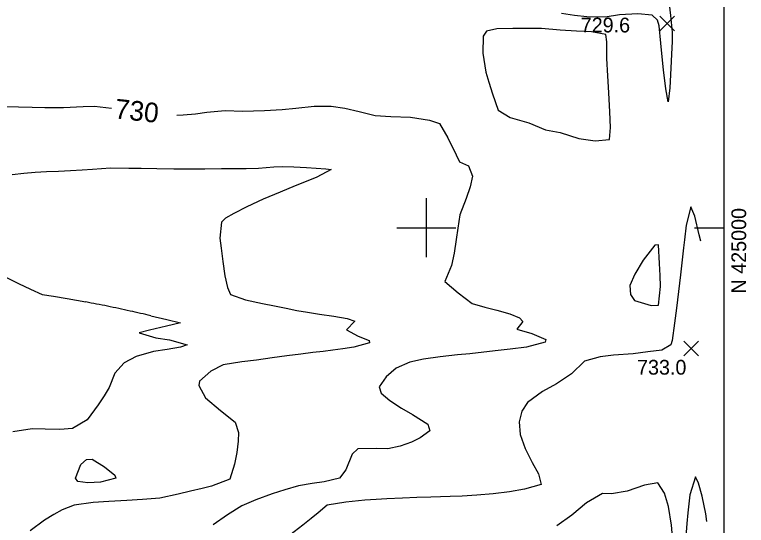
# Model space of a CAD drawing. Extents: x 2566079 to 2571326, y 424054 to 426896.
# Drawn here: x 2570581 to 2571326, y 424697 to 425217 of the extents above; entities that cross this region are included whole.
import ezdxf

# ---------------------------------------------------------------- set-up
doc = ezdxf.new("R2010")
doc.units = 0
for name, color, linetype in [('Contour_ADS_Label_Major', 7, 'Continuous'), ('Contour_ADS_Major', 7, 'Continuous'), ('Contour_ADS_Minor', 7, 'Continuous'), ('Contour_ADS_Spot_Elevation', 7, 'Continuous'), ('Contour_ADS_State_Plane_Border', 7, 'Continuous'), ('Contour_ADS_Tick', 7, 'Continuous')]:
    doc.layers.add(name, color=color, linetype=linetype)

# ---------------------------------------------------------------- blocks, each defined once
blk = doc.blocks.new('S890')
at = {"layer": 'Contour_ADS_Tick'}
for p, q in [((0, -0.5), (0, 0.5)), ((-0.5, 0), (0.5, 0))]:
    blk.add_line(p, q, dxfattribs=at)
blk = doc.blocks.new('S750')
at = {"layer": 'Contour_ADS_Spot_Elevation'}
for p, q in [((-0.5, 0.498), (0.5, -0.498)), ((-0.498, -0.5), (0.498, 0.5))]:
    blk.add_line(p, q, dxfattribs=at)

msp = doc.modelspace()

# ---------------------------------------------------------------- linework, layer by layer
at = {"layer": 'Contour_ADS_Major'}
for points in [[(2571247.16, 425227.51), (2571248.61, 425215.93), (2571250.07, 425199.08), (2571250.04, 425189.46), (2571249.56, 425176.51), (2571248.86, 425162.4), (2571247.71, 425142.46), (2571245.95, 425127.89), (2571243.63, 425141.31), (2571241.46, 425160.46), (2571240.06, 425173.97), (2571238.68, 425187.77), (2571237.04, 425205.47), (2571235.13, 425211.2), (2571229.74, 425216.37), (2571215.17, 425217.57), (2571196.61, 425216.58), (2571182, 425214.26), (2571163.35, 425214.64), (2571150.86, 425215.85), (2571137.48, 425217.8)], [(2570572.43, 425123.44), (2570584.86, 425122.91), (2570598.88, 425122.54), (2570611.93, 425122.33), (2570630.89, 425122.44), (2570650.66, 425123.4), (2570662.17, 425123.68), (2570679.69, 425121.7)], [(2570745.97, 425114.46), (2570752.47, 425114.71), (2570765.15, 425116.01), (2570776.61, 425117.61), (2570795.45, 425119.18), (2570813.15, 425118.71), (2570824, 425118.76), (2570835.27, 425119.11), (2570853.17, 425120.23), (2570867.04, 425121.75), (2570885.73, 425123.56), (2570903.1, 425123.76), (2570917.15, 425121.65), (2570931.79, 425118.29), (2570947.81, 425114.11), (2570963.77, 425113.03), (2570983.73, 425112.49), (2571003.3, 425109.32), (2571013.43, 425106.14), (2571021.97, 425091.45), (2571030.4, 425074.17), (2571033.81, 425066.9), (2571042.86, 425063.06), (2571046.9, 425052.34), (2571044.71, 425041.64), (2571040.63, 425029.6), (2571033.94, 425013.24), (2571031.92, 424999.7), (2571030.5, 424988.04), (2571028.3, 424974.02), (2571025.5, 424961.39), (2571018.8, 424945.4), (2571032.33, 424933.78), (2571046.66, 424922.84), (2571059.67, 424919.06), (2571071.8, 424916.03), (2571084.9, 424912.26), (2571094.73, 424908.29), (2571098.28, 424904.59), (2571092.1, 424896.92), (2571107.21, 424892.38), (2571121.6, 424886.2), (2571120.91, 424883.46), (2571102.05, 424878.39), (2571085.45, 424876.39), (2571072.92, 424874.98), (2571058.57, 424873.38), (2571044.31, 424871.83), (2571031.8, 424870.51), (2571014.09, 424868.68), (2570997.23, 424866.21), (2570983.19, 424863.06), (2570969.44, 424856.95), (2570959.18, 424848.35), (2570951.83, 424838.14), (2570954.17, 424831.68), (2570962.87, 424824.06), (2570974.84, 424816.4), (2570985.83, 424810.14), (2571001.65, 424800.06), (2571003.5, 424793.33), (2570993.8, 424786.18), (2570984.78, 424781.97), (2570973.27, 424777.65), (2570960.87, 424775.11), (2570949.02, 424775.42), (2570930.28, 424775.15), (2570924.56, 424769.61), (2570918.09, 424753.77), (2570911.75, 424745.05), (2570895.97, 424741.52), (2570883.75, 424739.8), (2570870.02, 424737.24), (2570855.98, 424733.48), (2570843.1, 424729.25), (2570826.45, 424723.17), (2570812.1, 424716.99), (2570797.61, 424707.76), (2570783.18, 424697.73)]]:
    msp.add_lwpolyline(points, dxfattribs=at)
at = {"layer": 'Contour_ADS_Minor'}
for points in [[(2571182.74, 425196.67), (2571168.12, 425199.36), (2571152.93, 425199.86), (2571136.09, 425200.98), (2571117.18, 425202.53), (2571098.7, 425202.68), (2571088.14, 425202.76), (2571071.65, 425202.18), (2571061.28, 425199.82), (2571057.75, 425194.91), (2571057.33, 425177.7), (2571060.6, 425158.18), (2571063.67, 425147.95), (2571067.29, 425136.03), (2571072.95, 425119.45), (2571085.27, 425112.25), (2571104.29, 425106.65), (2571121.34, 425099.59), (2571136.33, 425096.84), (2571155.2, 425090.72), (2571171.83, 425088.32), (2571186.25, 425089.76), (2571187.53, 425102.03), (2571186.78, 425118), (2571185.66, 425137.26), (2571184.63, 425154.46), (2571183.73, 425172.01), (2571183.53, 425189.19), (2571182.74, 425196.67)], [(2571236.19, 424982.46), (2571232.54, 424982.36), (2571220.61, 424967.08), (2571212.06, 424952.58), (2571207.03, 424941.18), (2571207.82, 424932.04), (2571211.67, 424926.05), (2571228.88, 424920.96), (2571236.35, 424921.07), (2571238.28, 424940.1), (2571237.91, 424951.4), (2571237.34, 424963.57), (2571236.19, 424982.46)], [(2570655.4, 424740.43), (2570645.28, 424741.71), (2570642.82, 424745.37), (2570648.36, 424759.17), (2570654.07, 424764.04), (2570660.08, 424764.41), (2570672.38, 424756.72), (2570682.93, 424748.24), (2570684.05, 424745.16), (2570668.49, 424741.22), (2570655.4, 424740.43)]]:
    msp.add_lwpolyline(points, close=True, dxfattribs=at)
for points in [[(2570578.56, 425054.19), (2570590.25, 425055.39), (2570601.78, 425056.38), (2570613.56, 425057.15), (2570625.8, 425057.69), (2570638.05, 425058.16), (2570649.7, 425058.73), (2570660.24, 425059.5), (2570678.67, 425060.83), (2570697.11, 425060.74), (2570709.7, 425060.44), (2570725.87, 425060.2), (2570743.13, 425060.05), (2570758.17, 425059.97), (2570774.71, 425059.93), (2570791.71, 425060.39), (2570803.2, 425060.36), (2570816.77, 425060.37), (2570829.05, 425060.64), (2570844.76, 425061.91), (2570853.2, 425062.21), (2570865.01, 425061.87), (2570877.96, 425061.16), (2570897.86, 425059.94), (2570903.07, 425059.2), (2570888.7, 425051.44), (2570879.28, 425047.72), (2570866.55, 425042.65), (2570851.14, 425036.3), (2570833.99, 425028.88), (2570817.38, 425021.29), (2570803.94, 425014.61), (2570795.58, 425009.57), (2570791.41, 425005.52), (2570789.96, 424989.29), (2570791.09, 424979.09), (2570792.74, 424965.48), (2570794.89, 424951.05), (2570797.55, 424939.12), (2570800.71, 424932.12), (2570816, 424926.51), (2570833.3, 424923), (2570845.35, 424920.47), (2570857.44, 424917.98), (2570868.35, 424915.89), (2570879.13, 424914.06), (2570891.44, 424912.2), (2570905.92, 424910.1), (2570919.29, 424907.71), (2570927.28, 424905.02)], [(2571279.17, 424986.19), (2571277.57, 424992.62), (2571273.28, 425011.75), (2571268.97, 425021.13), (2571264.54, 425002.55), (2571262.6, 424987.63), (2571261.63, 424979.49), (2571260.23, 424967.29), (2571258.47, 424952.02), (2571256.49, 424935.14), (2571254.44, 424918.16), (2571252.53, 424902.99), (2571250.05, 424885.39), (2571248.93, 424880.93), (2571239.52, 424875.43), (2571225.26, 424873.89), (2571210.4, 424871.64), (2571190.46, 424870.35), (2571176.77, 424868.59), (2571160.84, 424864.32), (2571147.76, 424851.24), (2571132.44, 424841.06), (2571118.09, 424833.42), (2571102.87, 424822.12), (2571097.32, 424813.45), (2571094.61, 424802.64), (2571095.63, 424789.76), (2571100.69, 424775.26), (2571107.73, 424761.12), (2571114.12, 424749.7), (2571116.74, 424738.87), (2571099.75, 424733.87), (2571084.74, 424731.28), (2571067.97, 424729.14), (2571051.38, 424727.78), (2571036.41, 424727.05), (2571024.38, 424726.65), (2571004.49, 424725.85), (2570990.22, 424725.44), (2570975.78, 424724.9), (2570959.81, 424724.04), (2570948.98, 424723.45), (2570937.29, 424722.71), (2570917.93, 424720.66), (2570899.01, 424717.68), (2570889.94, 424710.06), (2570882.74, 424704.16), (2570874.36, 424697.51), (2570861.12, 424687.37)], [(2570570.75, 424950.39), (2570585.15, 424943.39), (2570597.29, 424937.5), (2570609.01, 424932.18), (2570609.01, 424932.18)], [(2570609.01, 424932.18), (2570620.7, 424930.22), (2570634.58, 424927.85), (2570653.45, 424924.44)], [(2570719.7, 424910.41), (2570735.86, 424906.64), (2570749.98, 424903.36), (2570735.68, 424899.89), (2570718.22, 424895.68), (2570707.93, 424892.98), (2570724.59, 424887.99), (2570738.59, 424885.92), (2570756.48, 424880.97), (2570749.88, 424878.44), (2570736.25, 424876.09), (2570722.52, 424874.11), (2570704.87, 424869.12), (2570692.36, 424862.56), (2570683.06, 424852.03), (2570677.19, 424837.46), (2570672.1, 424828.81), (2570665.94, 424819.91), (2570654.78, 424804.4), (2570640.01, 424795.7), (2570627, 424794.72), (2570612.21, 424795.04), (2570598.94, 424795.37), (2570579.32, 424792.37)], [(2570927.28, 424905.02), (2570918.66, 424896.24), (2570930.69, 424889.51), (2570941.97, 424885.14), (2570942.01, 424882.88), (2570926.13, 424878.52), (2570915, 424876.73), (2570904.84, 424875.35), (2570895.09, 424874.18), (2570884.53, 424872.94), (2570872.2, 424871.39), (2570858.2, 424869.56), (2570842.94, 424867.53), (2570827.06, 424865.41), (2570812.28, 424863.41), (2570793.26, 424860.66), (2570780.77, 424854.05), (2570769.3, 424844.03), (2570768.5, 424839.32), (2570775.31, 424826.98), (2570790.44, 424814.17), (2570805.57, 424802.1), (2570808.69, 424791.56), (2570808.59, 424782.77), (2570807.17, 424771.42), (2570804.88, 424759.59), (2570799.88, 424744.12), (2570781.34, 424737.07), (2570771.82, 424734.76), (2570759.86, 424731.87), (2570747.33, 424728.88), (2570728.84, 424724.89), (2570711.08, 424723.35), (2570695.1, 424722.47), (2570676.82, 424721.42), (2570660.83, 424720.33), (2570641.73, 424717.72), (2570629.3, 424712.95), (2570620.87, 424708.32), (2570611.35, 424702.58), (2570596.72, 424691.72)], [(2571285.52, 424701.03), (2571284.23, 424708.87), (2571280.59, 424727), (2571277.02, 424740.27), (2571273.89, 424746.61), (2571268.16, 424728.1), (2571265.93, 424709.78), (2571264.95, 424699.04), (2571263.96, 424685.89)], [(2571250.78, 424681.35), (2571249.63, 424697.29), (2571246.34, 424716.34), (2571242.4, 424730.05), (2571235.54, 424740.34), (2571221.93, 424738.06), (2571204.2, 424731.97), (2571188.43, 424729.33), (2571179.32, 424729.47), (2571162.83, 424719.94), (2571148.09, 424707.47), (2571132.7, 424696.56)]]:
    msp.add_lwpolyline(points, dxfattribs=at)
for centre, radius, start, end in [((2570402.46, 423581.22), 1366.47, 78.47544, 79.41577), ((2570355.05, 423365.04), 1587.76, 77.50692, 78.35787), ((2570176.73, 422563.66), 2408.74, 76.97253, 77.48911)]:
    msp.add_arc(centre, radius, start, end, dxfattribs=at)
at = {"layer": 'Contour_ADS_State_Plane_Border'}
msp.add_line((2571272.93, 425000), (2571302.93, 425000), dxfattribs=at)
msp.add_lwpolyline([(2566079.33, 424077.11), (2571302.93, 424077.11), (2571302.93, 426873.74), (2566079.33, 426873.74), (2566079.33, 424077.11)], close=True, dxfattribs=at)

# ---------------------------------------------------------------- block references
at = {"layer": 'Contour_ADS_Spot_Elevation', "xscale": 15, "yscale": 15}
for p in [(2571244.97, 425207.72), (2571269.54, 424876.99)]:
    msp.add_blockref('S750', p, dxfattribs=at)
at = {"layer": 'Contour_ADS_Tick', "xscale": 60, "yscale": 60}
msp.add_blockref('S890', (2571000, 425000), dxfattribs=at)

# ---------------------------------------------------------------- texts
at = {"layer": 'Contour_ADS_Label_Major'}
msp.add_text('730', height=19.999, rotation=353.77184, dxfattribs=at).set_placement((2570682.19, 425111.37))
at = {"layer": 'Contour_ADS_Spot_Elevation'}
for s, p in [('729.6', (2571157.11, 425198.68)), ('733.0', (2571214.41, 424850.53))]:
    msp.add_text(s, height=15, dxfattribs=at).set_placement(p)
at = {"layer": 'Contour_ADS_State_Plane_Border'}
msp.add_text(' N 425000', height=15, rotation=90, dxfattribs=at).set_placement((2571325.43, 424927.5))

doc.saveas('drawing.dxf')
